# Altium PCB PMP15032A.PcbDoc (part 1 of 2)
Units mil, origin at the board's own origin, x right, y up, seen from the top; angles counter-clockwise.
Board outline 3900 x 2580 mil, 6 copper layers (Top Layer, Signal Layer 1, Signal Layer 2, Signal Layer 3, Signal Layer 4, Bottom Layer), stack 61.668 mil thick; 127 components, 51 nets, 282 pads, 427 vias.
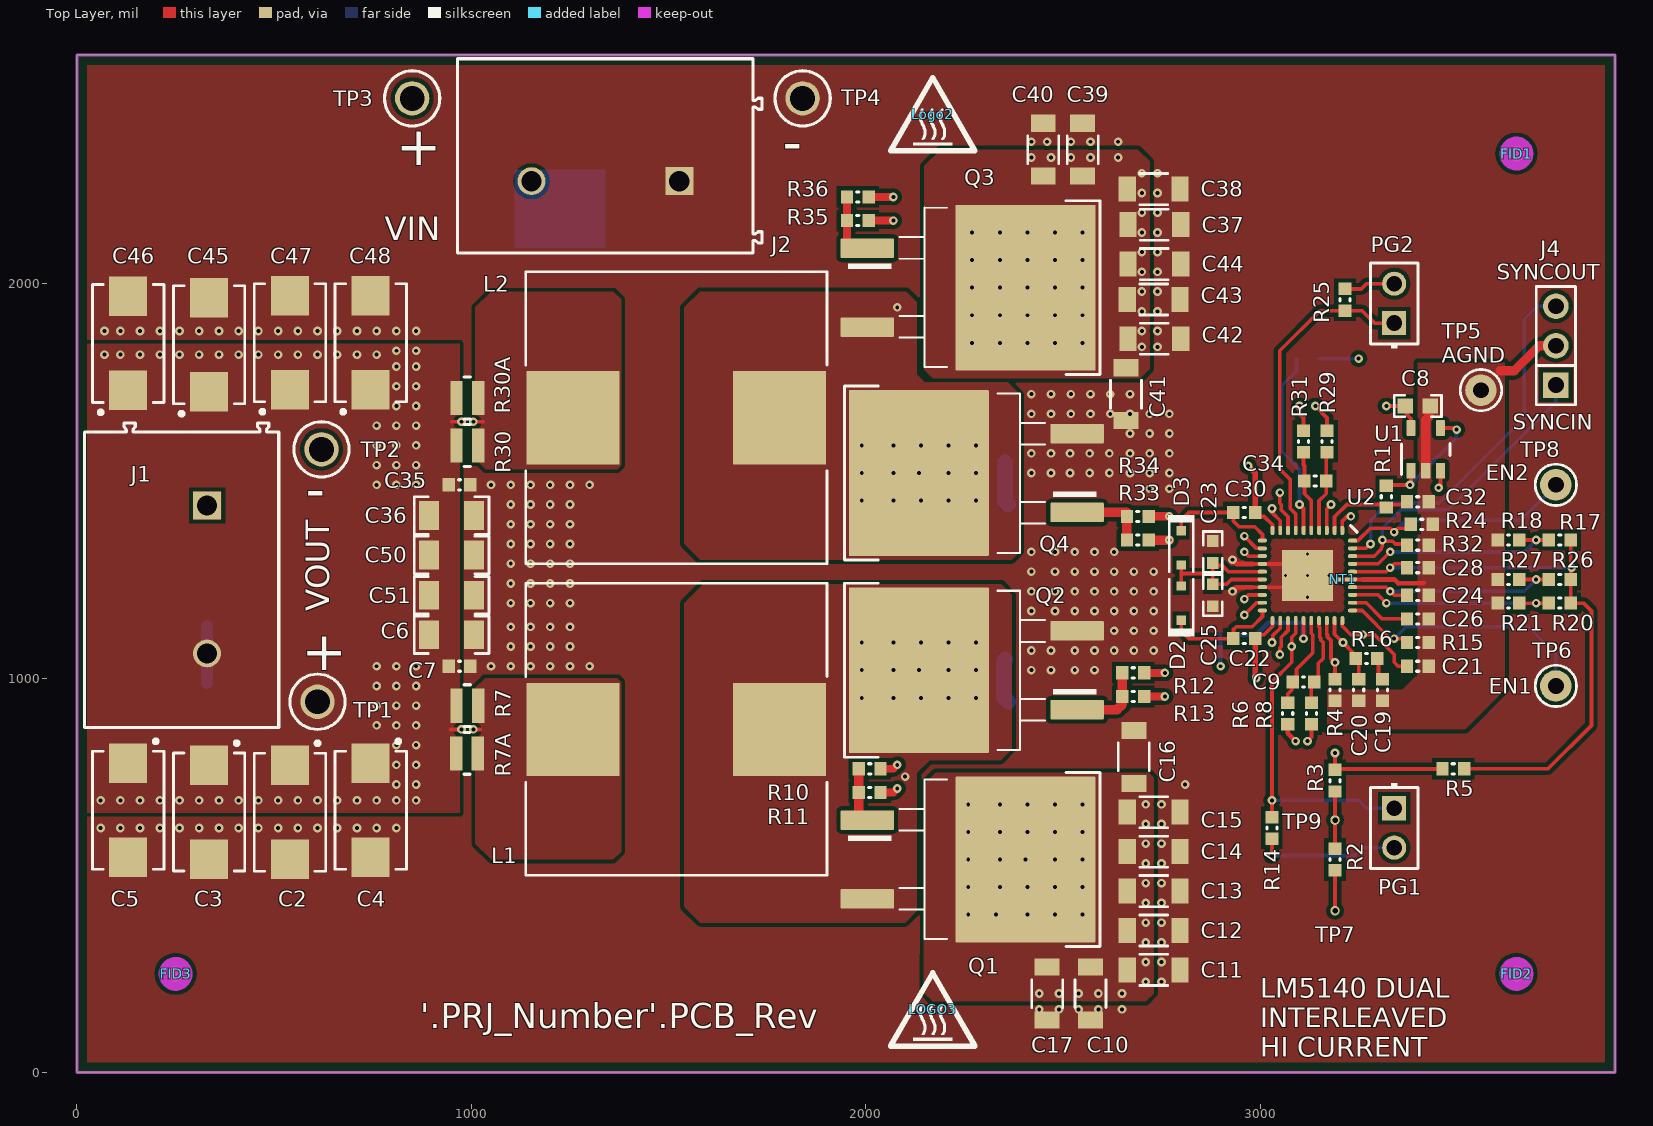
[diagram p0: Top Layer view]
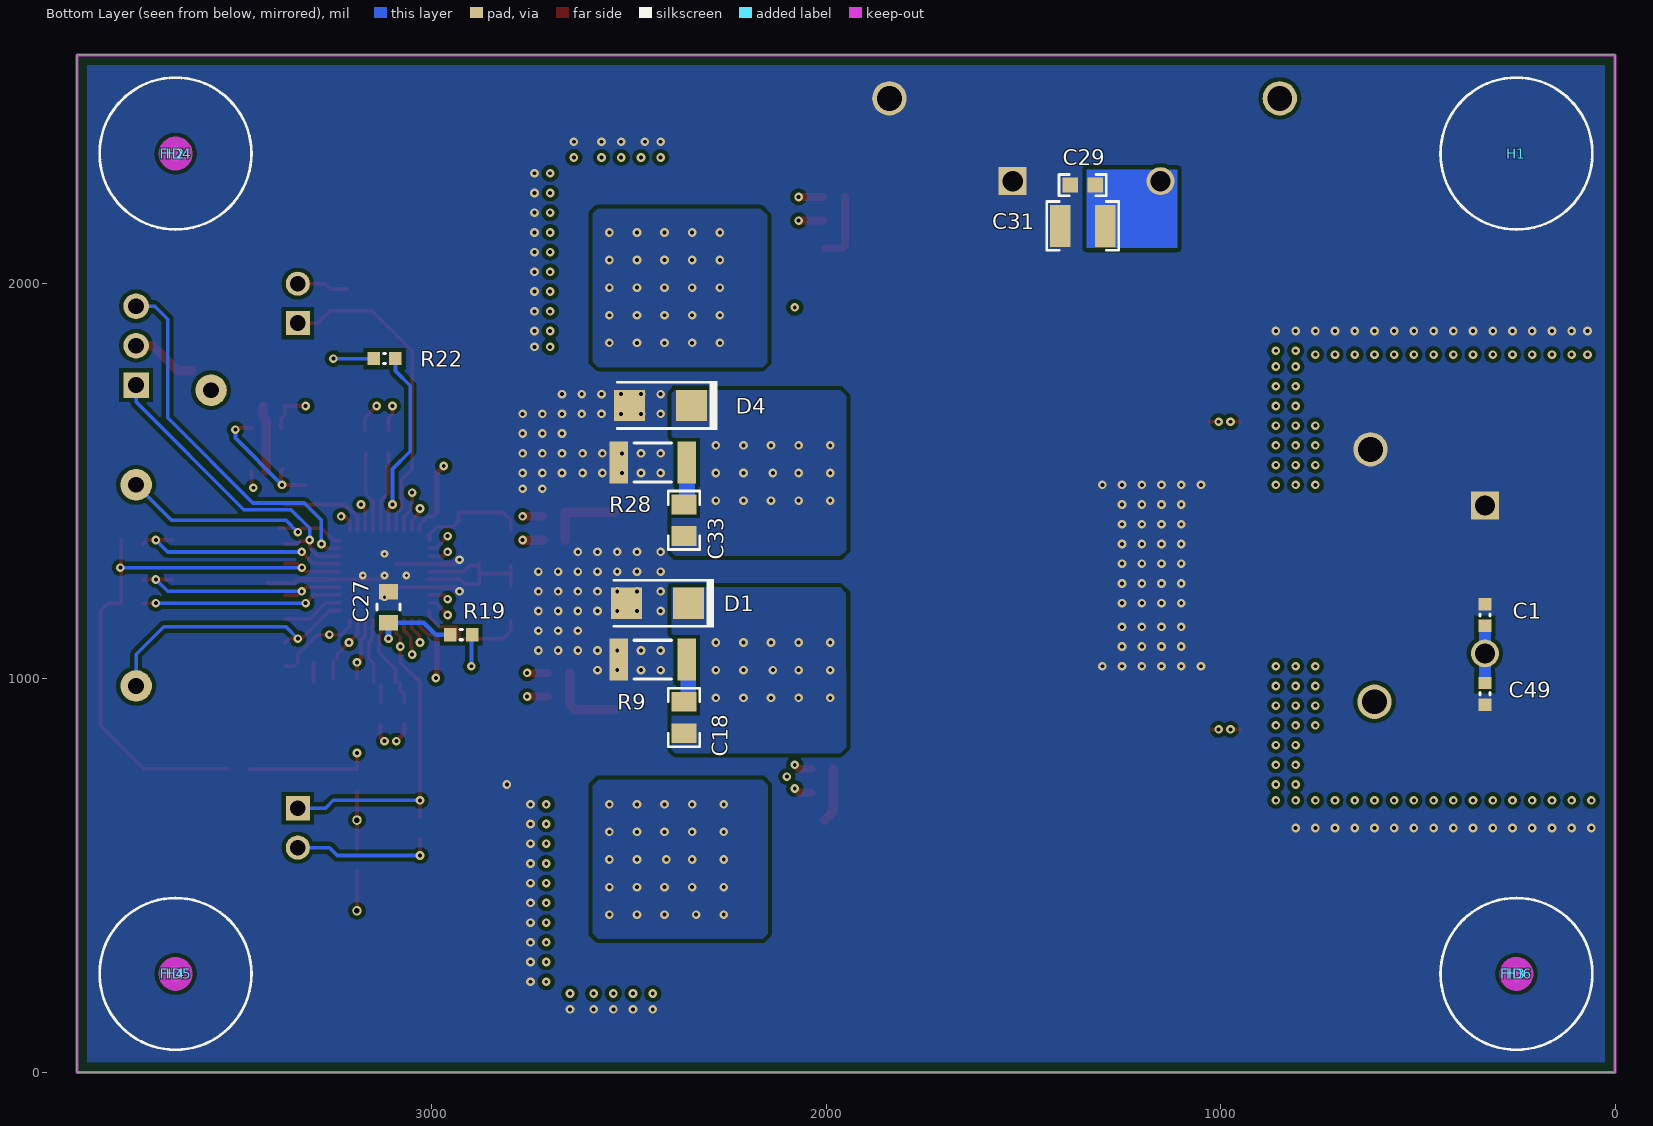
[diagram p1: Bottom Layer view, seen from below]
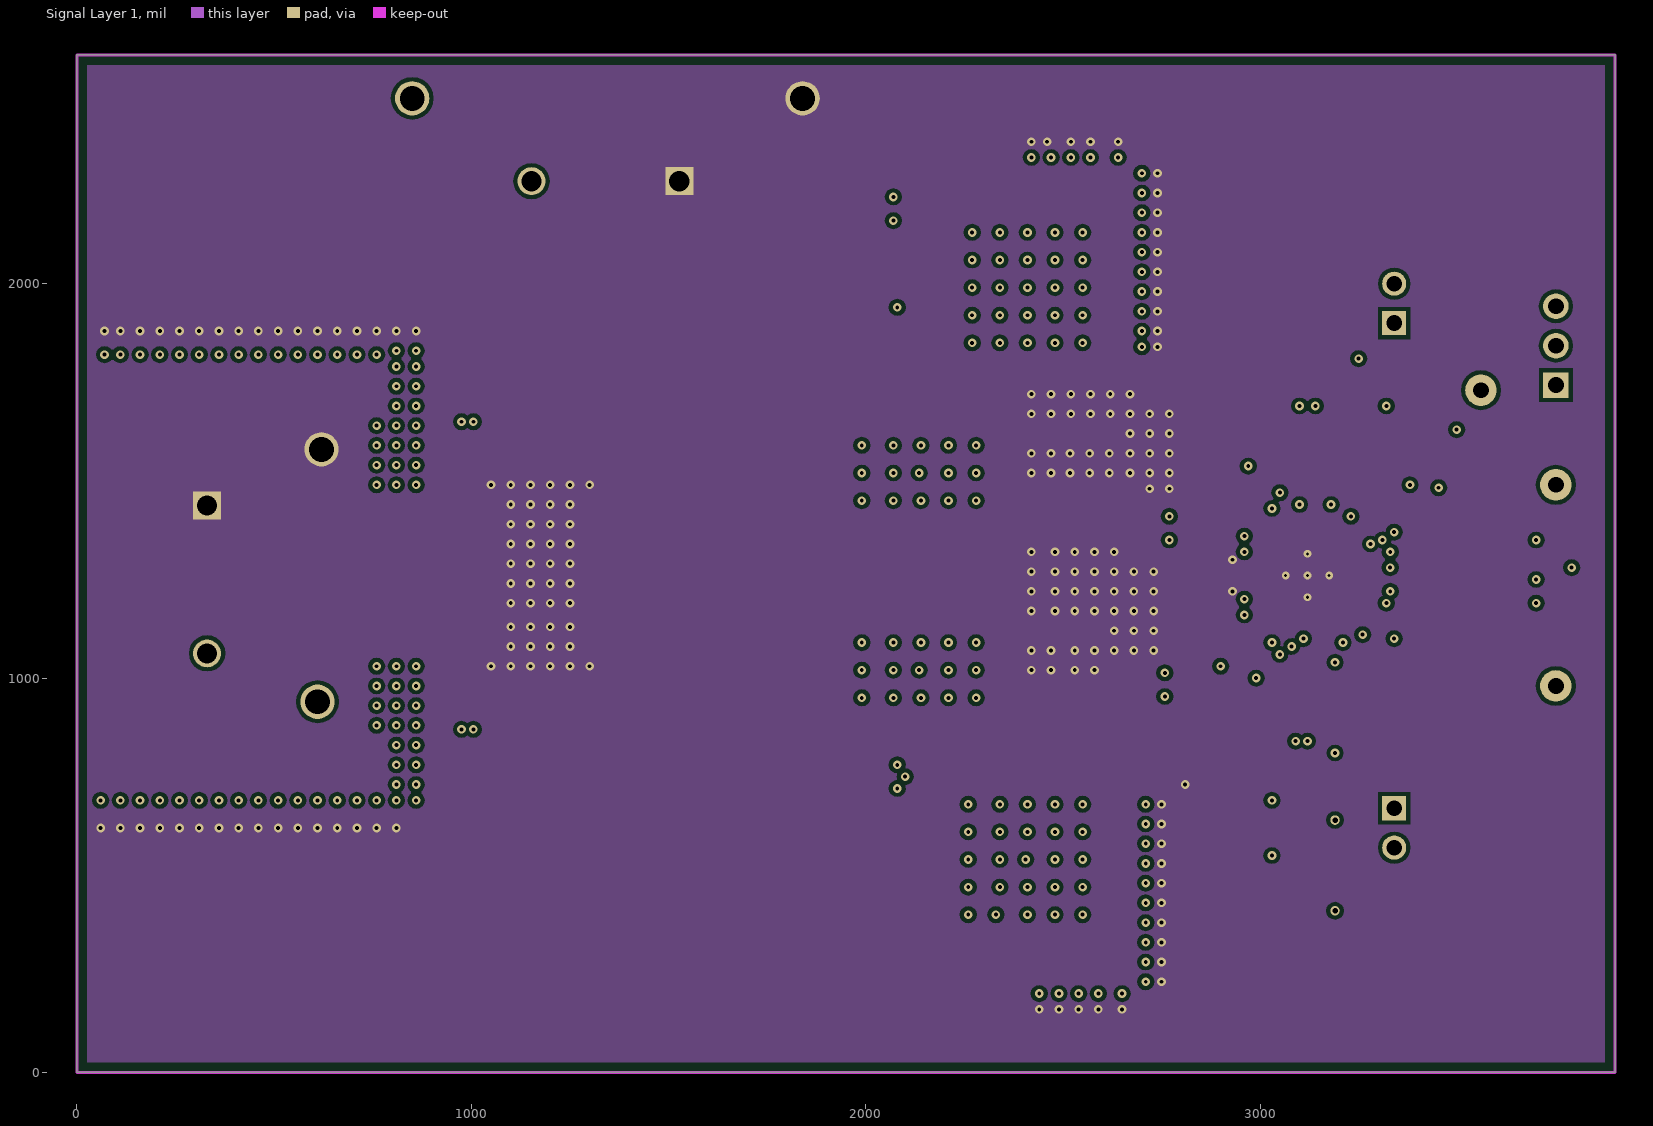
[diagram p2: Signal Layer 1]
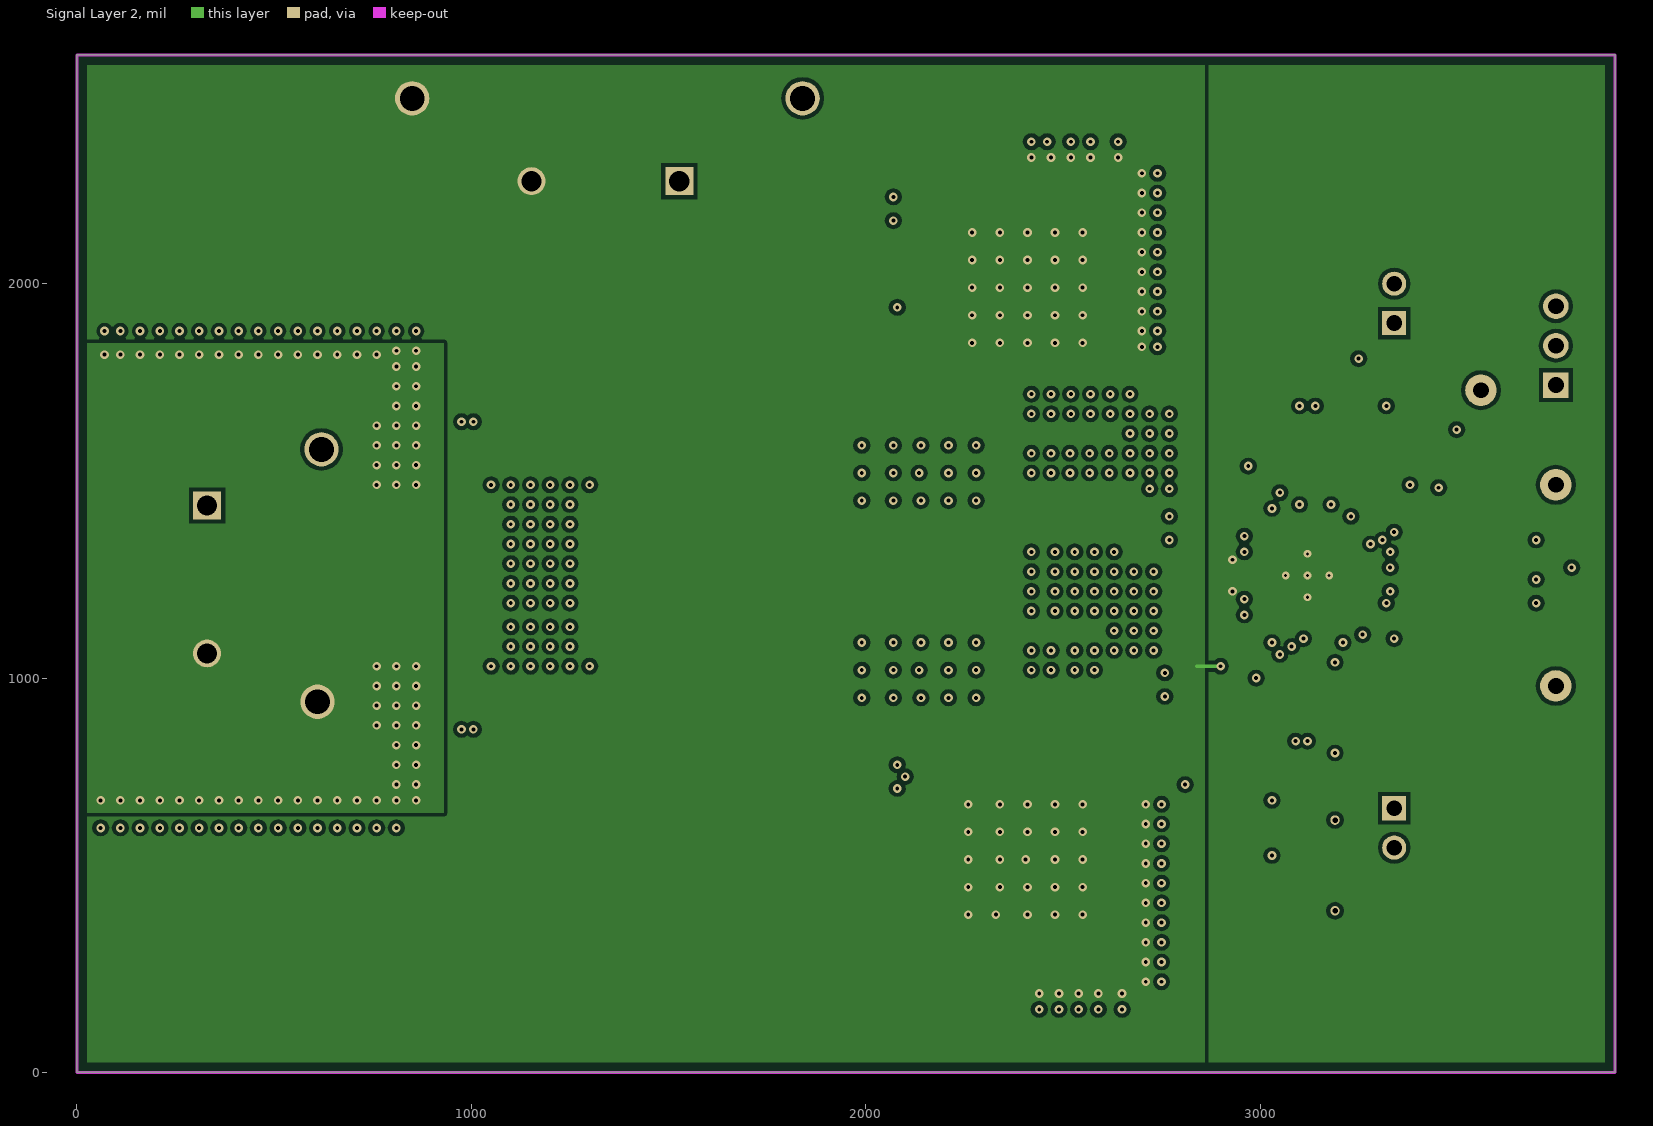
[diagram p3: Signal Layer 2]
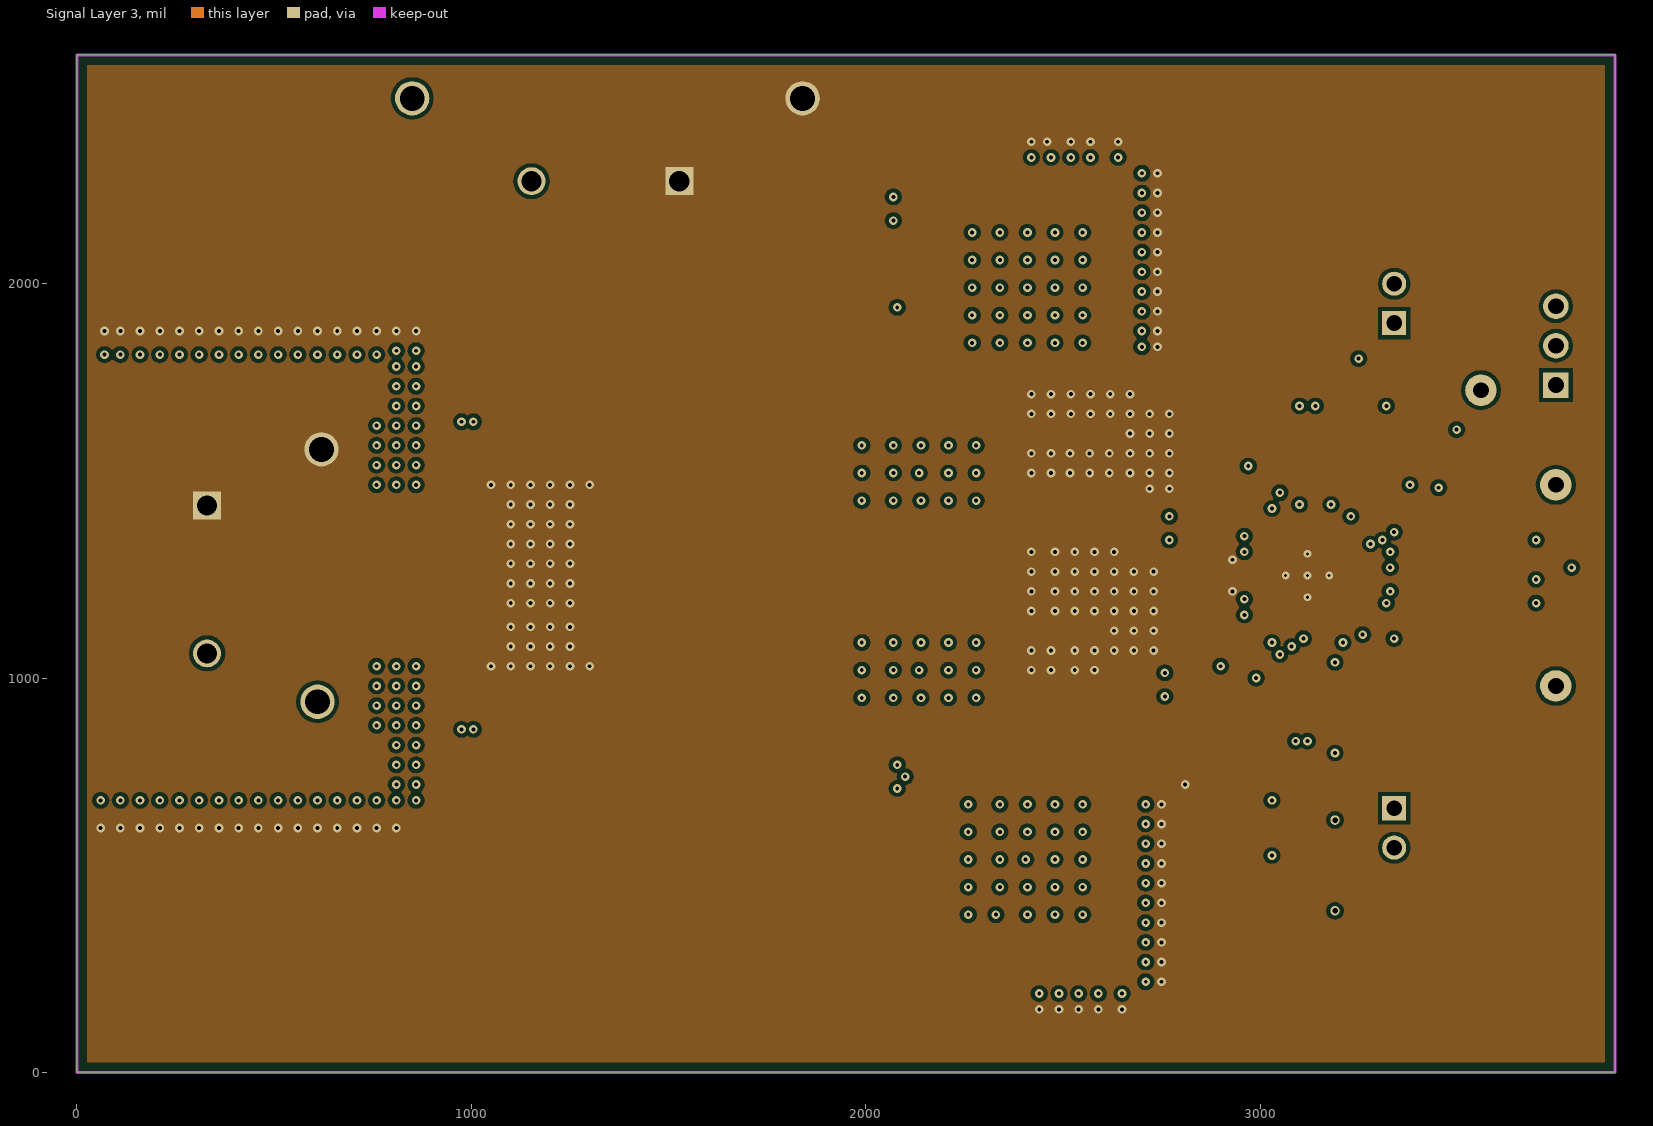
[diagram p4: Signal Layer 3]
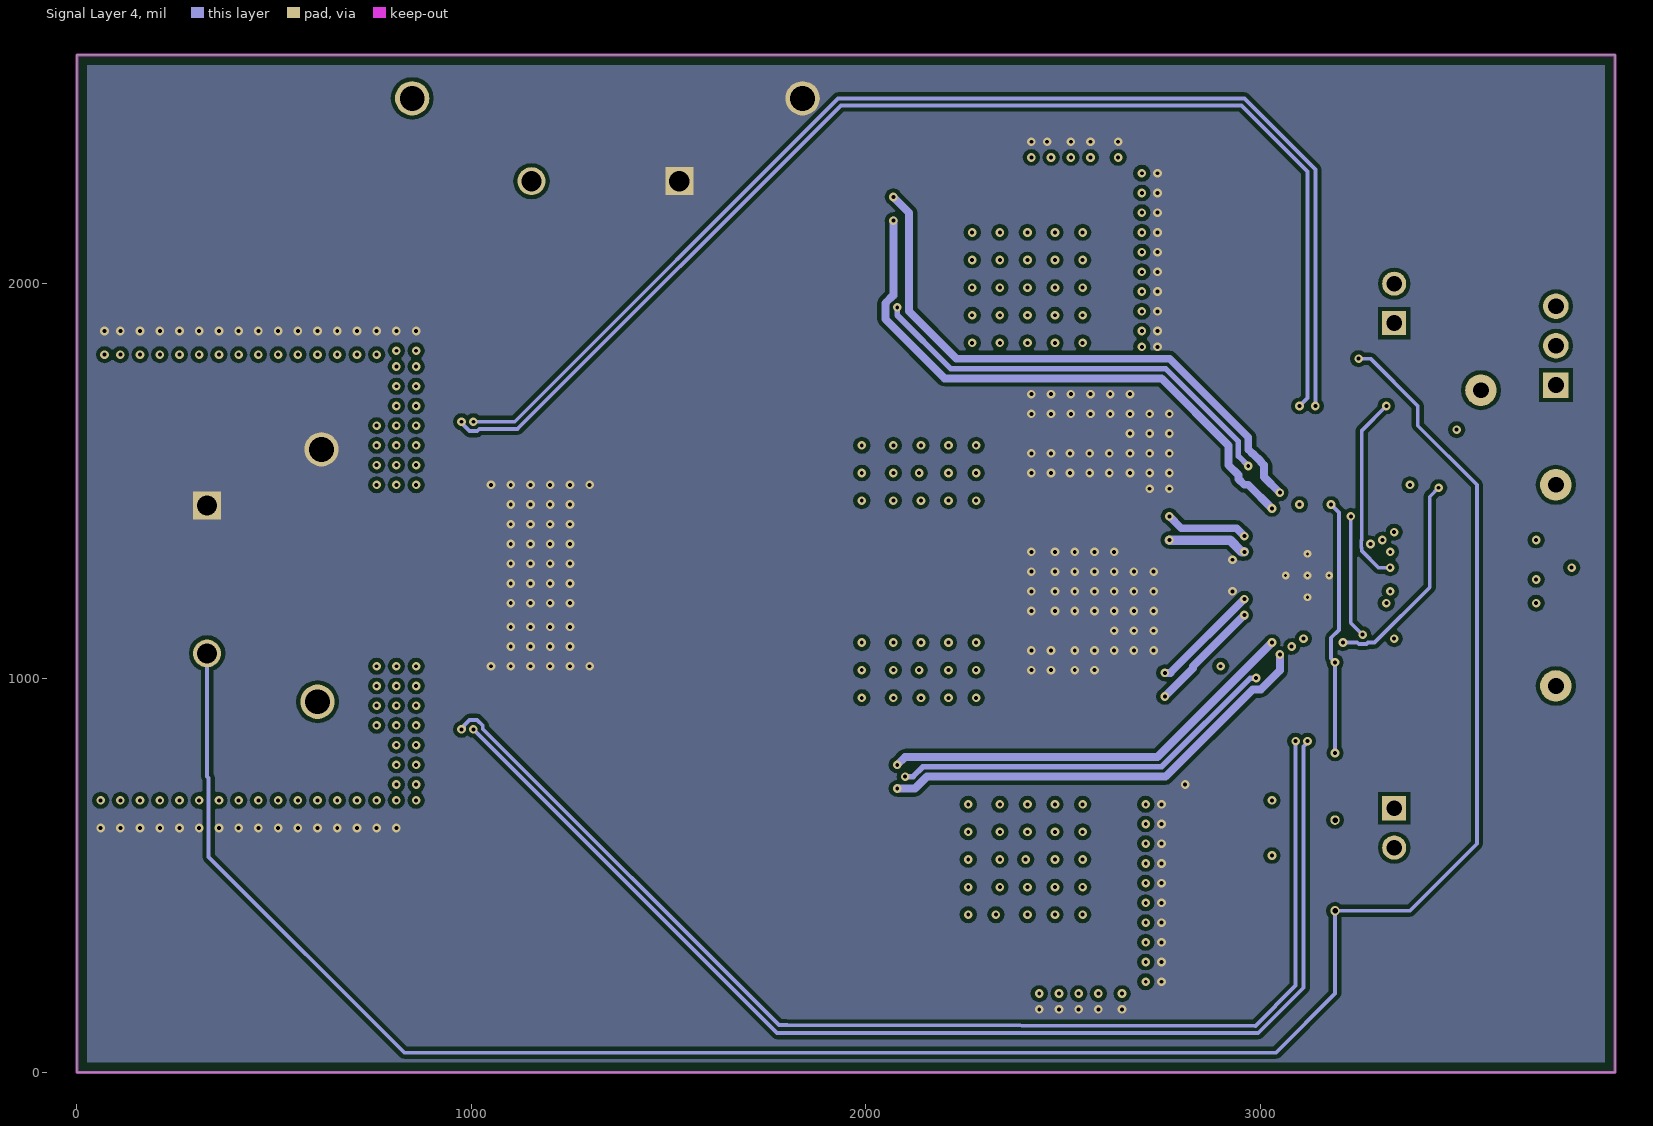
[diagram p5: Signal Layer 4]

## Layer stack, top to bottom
Top Solder: solder mask 0.4, Solder Resist, Dk 3.5
Top Layer: signal copper 2
Dielectric1: core 10, FR-4, Dk 4.8
Signal Layer 1: signal copper 1.417
Dielectric 2: prepreg 10, Dk 4.2
Signal Layer 2: signal copper 1.417
Dielectric 3: core 12, Dk 4.2
Signal Layer 3: signal copper 1.417
Dielectric 4: prepreg 10, Dk 4.2
Signal Layer 4: signal copper 1.417
Dielectric 5: core 10, Dk 4.2
Bottom Layer: signal copper 2
Bottom Solder: solder mask 0.4, Solder Resist, Dk 3.5

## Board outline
0,0 3900,0 3900,2580 0,2580

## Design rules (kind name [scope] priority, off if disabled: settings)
AcuteAngle [All] p1: minimum=4.50000000000000E+0001 checktracksonly=FALSE
AssemblyTestPointUsage [All] p1: valid=2
BoardOutlineClearance BoardOutlineClearance_MountingHoles [OnCopper and InComponentClass('Mounting Holes')] p1: gap=40
BoardOutlineClearance BoardOutlineClearance_Poly [OnCopper and IsPoly] p2: gap=25
BoardOutlineClearance [OnCopper and Not InComponentClass('Logo') and not InComponentClass('FiducialMark') and not InRegion(1000,500,4000,800) and not InPoly] p3: gap=40
Clearance Clearance_Keepouts [((IsTrack Or IsArc) And Not InPoly) And IsFree and IsKeepOut vs ((IsTrack Or IsArc) And Not InPoly) And IsFree and IsKeepOut] p1: gap=0
Clearance Clearance_Poly [InPolygon] p2: gap=10
Clearance [All] p3: gap=7.87
ComponentClearance ComponentClearance_Ficucial [HasFootprint('Fiducial10-20') vs HasFootprint('Bumpon_SJ61A2')] p1: gap=0 collisioncheckmode=3 verticalgap=0 showdistances=FALSE
ComponentClearance ComponentClearance_NetTie [HasFootprint('RWG0040A') vs HasFootprint('Net-Tie_10mil')] p2: gap=0 collisioncheckmode=3 verticalgap=0 showdistances=FALSE
ComponentClearance ComponentClearance_MountingHoles_FiducialMarks [InComponentClass('Mounting Holes') vs InComponentClass('FiducialMark')] p3: gap=50 collisioncheckmode=3 verticalgap=10 showdistances=FALSE
ComponentClearance ComponentClearance_Shunt [InComponentClass('Header') vs InComponentClass('Shunt')] p4: gap=0 collisioncheckmode=3 verticalgap=0 showdistances=FALSE
ComponentClearance ComponentClearance_Logo [InComponentClass('Logo')] p5: gap=50 collisioncheckmode=3 verticalgap=10 showdistances=FALSE
ComponentClearance ComponentClearance_ScrewToNut [(HasFootprint('NY PMS 440 0025 PH')) vs (HasFootprint('Keystone_1902C'))] p6: gap=5 collisioncheckmode=3 verticalgap=10 showdistances=FALSE
ComponentClearance ComponentClearance_MountingHoles [InComponentClass('Mounting Holes')] p7: gap=250 collisioncheckmode=3 verticalgap=100000 showdistances=FALSE
ComponentClearance ComponentClearance_SmallPassives [HasFootprint('0201*') or HasFootprint('0402*') or HasFootprint('0508') or HasFootprint('0603*') or HasFootprint('0612') or HasFootprint('0805*') or HasFootprint('0815*') or HasFootprint('0830*') or HasFootprint('1206*') or HasFootprint('1210*') or HasFootprint('1808*') or HasFootprint('1812*') or HasFootprint('1825*') or HasFootprint('2010*') or HasFootprint('2220*') or HasFootprint('2225*') or HasFootprint('2512*') or HasFootprint('2728*') or HasFootprint('3518*') vs HasFootprint('0201*') or HasFootprint('0402*') or HasFootprint('0508') or HasFootprint('0603*') or HasFootprint('0612') or HasFootprint('0805*') or HasFootprint('0815*') or HasFootprint('0830*') or HasFootprint('1206*') or HasFootprint('1210*') or HasFootprint('1808*') or HasFootprint('1812*') or HasFootprint('1825*') or HasFootprint('2010*') or HasFootprint('2220*') or HasFootprint('2225*') or HasFootprint('2512*') or HasFootprint('2728*') or HasFootprint('3518*')] p8: gap=14.96 collisioncheckmode=3 verticalgap=10 showdistances=FALSE
ComponentClearance ComponentClearance_THtoSMT [IsThruComponent vs IsSMTComponent] p9: gap=40 collisioncheckmode=3 verticalgap=30 showdistances=FALSE
ComponentClearance ComponentClearance_THtoTH [IsThruComponent vs IsThruComponent] p10: gap=30 collisioncheckmode=3 verticalgap=30 showdistances=FALSE
ComponentClearance [All] p11: gap=20 collisioncheckmode=3 verticalgap=10 showdistances=FALSE
DiffPairsRouting [All] p1: maxlimit=100 minlimit=10 mostfreqgap=10 toplayer_minwidth=15 toplayer_maxwidth=15 toplayer_prefwidth=15 midlayer1_minwidth=15 midlayer1_maxwidth=15 midlayer1_prefwidth=15 midlayer2_minwidth=15 midlayer2_maxwidth=15 midlayer2_prefwidth=15 midlayer3_minwidth=15 midlayer3_maxwidth=15 midlayer3_prefwidth=15 midlayer4_minwidth=15 midlayer4_maxwidth=15 midlayer4_prefwidth=15 bottomlayer_minwidth=15 bottomlayer_maxwidth=15 bottomlayer_prefwidth=15 maxuncoupledlength=1000
FabricationTestPointUsage TestPointUsage [All] p1: valid=2 allowmultiple=FALSE
FabricationTestpoint Testpoint [All] p1: side=3 testpointundercomponent=TRUE minsize=40 maxsize=100 preferedsize=60 minholesize=0 maxholesize=40 preferedholesize=32 testpointgrid=1 allowsidetop=TRUE allowsidebottom=TRUE usegrid=TRUE gridtolerance=0.01
FanoutControl Fanout_LCC [IsLCC] p1: bgadir=Out bgaviamode=Centered fanoutstyle=Auto fanoutdirection=Alternating viagrid=1 // Fanout_LCC (Default Rule)
FanoutControl Fanout_BGA [IsBGA] p2: bgadir=Out bgaviamode=Centered fanoutstyle=Auto fanoutdirection=Alternating viagrid=1 // Fanout_BGA (Default Rule)
FanoutControl Fanout_Default [All] p4: bgadir=Out bgaviamode=Centered fanoutstyle=Auto fanoutdirection=Alternating viagrid=1 // Fanout_Default (Default Rule)
FanoutControl Fanout_Small [(CompPinCount < 5)] p5: bgadir=Out bgaviamode=Centered fanoutstyle=Auto fanoutdirection=OutThenIn viagrid=1 // Fanout_Small (Default Rule)
HoleSize [All] p1: absolutevalues=TRUE maxlimit=251 minlimit=7.87 maxpercent=80.000 minpercent=20.000
MinimumAnnularRing MinimumAnnularRing_ThermalPadVias [IsVia and InAnyComponent] p1: minimumring=5.91
MinimumAnnularRing [All] p2: minimumring=5
MinimumSolderMaskSliver MinimumSolderMaskSliver_Logo [InComponentClass('Logo') vs InComponentClass('Logo')] p1: minsoldermaskwidth=0.7
MinimumSolderMaskSliver [All] p2: minsoldermaskwidth=3.94
PlaneConnect [All] p1: planeconnectstyle=Relief reliefexpansion=10 reliefentries=4 reliefconductorwidth=10 reliefairgap=10
PolygonConnect [All] p1: connectstyle=Direct reliefconductorwidth=10 reliefentries=4 polygonreliefangle="90 Angle" airgapwidth=10
RoutingVias ThermalPadVias [IsVia and InAnyComponent] p1: holewidth=7.87 width=19.68 viastyle="Through Hole" minholewidth=7.87 minwidth=19.68 maxholewidth=12.99 maxwidth=23.62
RoutingVias [All] p2: holewidth=10 width=22 viastyle="Through Hole" minholewidth=7.87 minwidth=20 maxholewidth=40 maxwidth=65
SilkToBoardRegionClearance [Not ((IsComment or IsDesignator) And (Hide <> 'False')) and not InRegion(1000,500,4000,800)] p1:
SilkToSilkClearance SilkToSilkClearance_Pb-FreeLogo [(HasFootprint('Pb-Free_Overlay_Medium') OR HasFootprint('Pb-Free_Overlay_Small')) vs (HasFootprint('Pb-Free_Overlay_Medium') OR HasFootprint('Pb-Free_Overlay_Small'))] p1: silktosilkclearance=0
SilkToSilkClearance [All] p2: silktosilkclearance=4
SilkToSolderMaskClearance SilkToComponentPadClearance [IsPad and InAnycomponent] p1: minsilkscreentomaskgap=5 clearancetoexposedcopper=TRUE
SilkToSolderMaskClearance "Silk to Solder Mask Opening" [All] p2: minsilkscreentomaskgap=4 clearancetoexposedcopper=FALSE
SolderMaskExpansion [All] p1: expansion=1.97
Width [All] p1: maxlimit=100 minlimit=6 preferedwidth=10 checkconnectedcopper=TRUE
15 further rules are at their usual default settings.

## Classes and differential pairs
component class PMP15032A: C1 C2 C3 C4 C5 C6 C7 C8 C9 C10 C11 C12 C13 C14 C15 C16 C17 C18 C19 C20 C21 C22 C23 C24 C25 C26 C27 C28 C29 C30 C31 C32 C33 C34 C35 C36 C37 C38 C39 C40 C41 C42 C43 C44 C45 C46 C47 C48 C49 C50 C51 D1 D2 D3 D4 J1 J2 J4 L1 L2 NT1 PG1 PG2 Q1 Q2 Q3 Q4 R1 R2 R3 R4 R5 R6 R7 R7A R8 R9 R10 R11 R12 R13 R14 R15 R16 R17 R18 R19 R20 R21 R22 R24 R25 R26 R27 R28 R29 R30 R30A R31 R32 R33 R34 R35 R36 TP1 TP2 TP3 TP4 TP5 TP6 TP7 TP8 TP9 U1 U2
component class PMP15032A-HW: FID1 FID2 FID3 FID4 FID5 FID6 H1 H2 H3 H4 Logo2 LOGO3

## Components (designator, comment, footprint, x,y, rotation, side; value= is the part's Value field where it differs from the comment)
C1 "GRM188R72A104KA35D" 0603L 330,1160 r270 bottom
C2 "100µF" 7343-31 540,660 r270 top
C3 "100µF" 7343-31 335.14,660.22 r270 top
C4 "100µF" 7343-31 744.86,664.86 r270 top
C5 "100µF" 7343-31 130,664.86 r270 top
C6 "C3216X5R1C476M160AB" 1206 950,1110 r0 top
C7 "GRM188R72A104KA35D" 0603L 970,1030 r180 top
C8 "0.1uF" 0603 3400,1690 r0 top
C9 "06031A330JAT2A" 0603L 3110,990 r180 top
C10 "CGA5L3X7S2A225M160AB" 1206_190 2570,200 r90 top
C11 "CGA5L3X7S2A225M160AB" 1206_190 2730,260 r180 top
C12 "CGA5L3X7S2A225M160AB" 1206_190 2730,360 r180 top
C13 "CGA5L3X7S2A225M160AB" 1206_190 2730,460 r180 top
C14 "CGA5L3X7S2A225M160AB" 1206_190 2730,560 r180 top
C15 "CGA5L3X7S2A225M160AB" 1206_190 2730,660 r180 top
C16 "CGA5L3X7S2A225M160AB" 1206_190 2680,800 r270 top
C17 "CGA5L3X7S2A225M160AB" 1206_190 2460,200 r90 top
C18 "08051A471JAT2A" 0805_HV 2360.58,900.06 r90 bottom
C19 "GRM188R71E103KA01D" 0603L 3310,970 r90 top
C20 "C0603C470J5GACTU" 0603L 3250,970 r270 top
C21 "C1608X7R1E105K080AB" 0603L 3400,1030 r0 top
C22 "CGA3E3X7R1H334K080AB" 0603L 2960,1100 r180 top
C23 "C0603C225M8PACTU" 0603_HV 2880,1320 r90 top
C24 "GRM188R71H103KA01D" 0603L 3400,1210 r0 top
C25 "C0603C225M8PACTU" 0603_HV 2880,1210 r90 top
C26 "GRM188R71H103KA01D" 0603L 3400,1150 r0 top
C27 "GRM21BR72A474KA73L" 0805_HV1 3110,1180 r270 bottom
C28 "C1608X7R1E105K080AB" 0603L 3400,1280 r0 top
C29 "GRM188R72A104KA35J" 0603 1350,2250 r0 bottom
C30 "CGA3E3X7R1H334K080AB" 0603L 2960,1420 r180 top
C31 "CGA6M3X7S2A475K200AB" 1210_220 1349.66,2146.77 r0 bottom
C32 "C0603C470J5GACTU" 0603L 3400,1447 r180 top
C33 "08051A471JAT2A" 0805_HV 2360.58,1400.06 r270 bottom
C34 "06031A330JAT2A" 0603L 3140,1500 r0 top
C35 "GRM188R72A104KA35D" 0603L 970,1490 r180 top
C36 "C3216X5R1C476M160AB" 1206 950,1412.02 r0 top
C37 "CGA5L3X7S2A225M160AB" 1206_190 2731.81,2149.78 r0 top
C38 "CGA5L3X7S2A225M160AB" 1206_190 2730,2240 r0 top
C39 "CGA5L3X7S2A225M160AB" 1206_190 2550,2340 r90 top
C40 "CGA5L3X7S2A225M160AB" 1206_190 2450,2340 r90 top
C41 "CGA5L3X7S2A225M160AB" 1206_190 2660,1720 r270 top
C42 "CGA5L3X7S2A225M160AB" 1206_190 2731.81,1860.22 r0 top
C43 "CGA5L3X7S2A225M160AB" 1206_190 2730,1960 r0 top
C44 "CGA5L3X7S2A225M160AB" 1206_190 2731.81,2049.78 r0 top
C45 "100µF" 7343-31 335.14,1845.14 r90 top
C46 "100µF" 7343-31 130,1848.59 r90 top
C47 "100µF" 7343-31 540,1850 r90 top
C48 "100µF" 7343-31 744.86,1850 r90 top
C49 "GRM188R72A104KA35D" 0603L 330,960 r90 bottom
C50 "C3216X5R1C476M160AB" 1206 950,1312.02 r0 top
C51 "C3216X5R1C476M160AB" 1206 950,1210 r0 top
D1 "B170-13-F" SMA 2428.19,1189.78 r0 bottom
D2 "PMEG6010CEJ,115" SOD-323F 2800,1190 r90 top
D3 "PMEG6010CEJ,115" SOD-323F 2800,1330 r270 top
D4 "B170-13-F" SMA 2420,1691.41 r0 bottom
FID1 "Fiducial" Fiducial10-20 3650,2330 r0 top
FID2 "Fiducial" Fiducial10-20 3650,250 r0 top
FID3 "Fiducial" Fiducial10-20 250,250 r0 top
FID4 "Fiducial" Fiducial10-20 3650,2330 r90 bottom
FID5 "Fiducial" Fiducial10-20 3650,250 r90 bottom
FID6 "Fiducial" Fiducial10-20 250,250 r90 bottom
H1 "SJ61A2" Bumpon_SJ61A2 250,2330 r180 bottom locked
H2 "SJ61A2" Bumpon_SJ61A2 3650,2330 r180 bottom locked
H3 "SJ61A2" Bumpon_SJ61A2 250,250 r180 bottom locked
H4 "SJ61A2" Bumpon_SJ61A2 3650,250 r180 bottom locked
J1 "1714971" Phoenix_1714971 330,1250 r270 top
J2 "1714971" Phoenix_1714971 1340,2260 r180 top
J4 "PBC03SAAN" PBC03SAAN 3750,1842.85 r90 top
L1 "7443556190" WE-HCB_1890 1520,870 r180 top
L2 "7443556190" WE-HCB_1890 1520,1660 r0 top
Logo2 "CAUTION HOT SURFACE" IEC_HotSurface_Small 2170,2430 r0 top (schematic designator LOGO2)
LOGO3 "CAUTION HOT SURFACE" IEC_HotSurface_Small 2170,160 r0 top
NT1 "Net-Tie" Net-Tie_10mil 3210,1250 r180 top net-tie
PG1 "PEC01DAAN" Sullins_PxC01DAAN 3340,620 r270 top
PG2 "PEC01DAAN" Sullins_PxC01DAAN 3340,1950 r90 top
Q1 "FDD9407L_F085" DDPAK 2250,540 r0 top
Q2 "FDD9407L_F085" DDPAK 2290,1020 r180 top
Q3 "FDD9407L_F085" DDPAK 2250,1990 r0 top
Q4 "FDD9407L_F085" DDPAK 2290,1520 r180 top
R1 "0" 0603L 3320,1460 r90 top
R2 "CRCW060310R0FKEA" 0603L 3190,540 r270 top
R3 "CRCW060363K4FKEA" 0603L 3190,740 r270 top
R4 "CRCW060320K0FKEA" 0603L 3190,970 r90 top
R5 "0" 0603L 3490,770 r0 top
R6 "CRCW06030000Z0EA" 0603L 3070,910 r270 top
R7 "KRL2012M-R005-F-T1" KRL2012 990,930 r0 top
R7A "KRL2012M-R005-F-T1" KRL2012 989.18,809.19 r0 top
R8 "CRCW060349R9FKEA" 0603L 3130,910 r270 top
R9 "CRCW20108R20JNEF" 2010L 2440,1046.77 r180 bottom
R10 "CRCW06034R99FKEA" 0603L 2010,770 r0 top
R11 "CRCW06030000Z0EA" 0603L 2010,710 r0 top
R12 "CRCW06034R99FKEA" 0603L 2678.31,1013.27 r0 top
R13 "CRCW06034R99FKEA" 0603L 2678.31,953.27 r0 top
R14 "CRCW060310K0JNEA" 0603L 3030,620 r90 top
R15 "100k" 0603L 3400,1090 r180 top
R16 "CRCW060310K0FKEA" 0603L 3270,1050 r180 top
R17 "RC0603JR-070RL" 0603L 3760,1350 r0 top
R18 "0" 0603L 3630,1350 r180 top
R19 "CRCW06030000Z0EA" 0603L 2925.55,1110 r180 bottom
R20 "CRCW06030000Z0EA" 0603L 3760,1190 r180 top
R21 "0" 0603L 3630,1190 r0 top
R22 "0" 0603L 3120,1810 r180 bottom
R24 "100k" 0603L 3410,1390 r180 top
R25 "CRCW060310K0JNEA" 0603L 3215.29,1959.14 r90 top
R26 "0" 0603L 3760,1250 r0 top
R27 "0" 0603L 3630,1250 r180 top
R28 "CRCW20108R20JNEF" 2010L 2440,1546.77 r180 bottom
R29 "CRCW060349R9FKEA" 0603L 3170,1600 r90 top
R30 "KRL2012M-R005-F-T1" KRL2012 990,1590 r180 top
R30A "KRL2012M-R005-F-T1" KRL2012 990,1710 r180 top
R31 "CRCW06030000Z0EA" 0603L 3110,1600 r90 top
R32 "CRCW060310K0FKEA" 0603L 3400,1337 r180 top
R33 "CRCW06034R99FKEA" 0603L 2690,1350 r180 top
R34 "CRCW06034R99FKEA" 0603L 2690,1410 r180 top
R35 "CRCW06034R99FKEA" 0603L 1980,2160 r180 top
R36 "CRCW06030000Z0EA" 0603L 1980,2220 r180 top
TP1 "+VOUT1" Keystone5010 610,940 r0 top
TP2 "GND" Keystone5011 620,1580 r0 top
TP3 "+VIN" Keystone5010 850,2470 r0 top
TP4 "GND" Keystone5011 1840,2470 r0 top
TP5 "5001" Keystone5001 3560,1730 r0 top
TP6 "EN1" Keystone5002 3750,980 r90 top
TP7 "TESTPOINT" TP_VIA_024RND014 3190,410 r90 top
TP8 "EN2" Keystone5002 3750,1490 r180 top
TP9 "TESTPOINT" TP_VIA_024RND014 3190,640 r90 top
U1 "LMP7701MF" DBV0005A_N 3420,1580 r90 top
U2 "LM5140QRWGRQ1" RWG0040A 3120,1260 r270 top

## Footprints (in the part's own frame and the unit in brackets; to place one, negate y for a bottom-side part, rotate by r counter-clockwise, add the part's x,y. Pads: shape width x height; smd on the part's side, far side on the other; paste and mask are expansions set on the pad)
0603 [mm] "0603 from SM-752 data"
  rect 1x0.95 smd: 1(-0.8,0) 2(0.8,0)
  silkscreen extent -1.52,-0.69 1.52,0.69, body extent -0.87,-0.47 0.87,0.47, height 1
0603_HV [mil] "Ernesto recommended land pattern.  26 mil between pads."
  rect 30x30 smd: 1(-28,0) 2(28,0)
  silkscreen extent -52,-24 52,24, body extent -34,-19 34,19, height 39
0603L [mm] "0603 from SM-752 data"
  rect 0.8x0.85 smd: 1(-0.7,0) 2(0.7,0)
  silkscreen extent -0.07,-0.33 0.07,0.33, body extent -0.87,-0.47 0.87,0.47, height 1
0805_HV [mil] "0805 with 30mil clearance between pads"
  rect 50x63 smd: 1(-40,0) 2(40,0)
  silkscreen extent -74,-40 74,40, body extent -43,-29 43,29, height 57
0805_HV1 [mm] "Custom footprint based on analyzing multiple manufacturer recommendations"
  rrect10% 1x1.25 smd: 1(-1,0) 2(1,0)
  silkscreen extent -0.2,-0.75 0.2,0.75, body extent -1.1,-0.72 1.1,0.73, height 1.45
1206 [mm] "1206 from SM-752 data"
  rect 1.3x1.85 smd: 1(-1.45,0) 2(1.45,0)
  silkscreen extent -2.4,-1.21 2.4,1.21, body extent -1.7,-0.9 1.7,0.9, height 1.35
1206_190 [mm] "1206_190"
  rect 1.1x1.6 smd: 1(-1.7,0) 2(1.7,0)
  silkscreen extent -0.9,-1 0.9,1, body extent -1.75,-0.95 1.75,0.95, height 1.9
1210_220 [mm] "1210"
  rect 1.3x2.7 smd: 1(-1.45,0) 2(1.45,0)
  silkscreen extent -2.32,-1.57 2.32,1.57, body extent -1.7,-1.35 1.7,1.35, height 2.2
2010L [mm]
  rect 1.2x2.7 smd: 1(-2.2,0) 2(2.2,0)
  silkscreen extent -1.2,-1.25 1.2,1.25, body extent -2.73,-1.45 2.73,1.45, height 1.66
7343-31 [mm] "Medium Density based on Kemet T495 dimensions"
  rect 2.55x2.45 smd: 1(-3.025,0) 2(3.025,0)
  silkscreen extent -4.56,-2.3 3.8,2.3, body extent -3.8,-2.3 3.8,2.3, height 3.1
Bumpon_SJ61A2 [mil] "3M Hemispherical Bumpon transparent"
  round 1 on Mech4: 0(0,0)
  silkscreen extent -192,-192 192,192, body extent -193,-192 193,192, height 250
DBV0005A_N [mm] "SOT23, 5-Leads, Body 2.9x1.6mm, Pitch 0.95mm, Lead Span 2.8mm, IPC Medium Density"
  rrect17% 1x0.6 smd: 1(-1.375,0.95) 2(-1.375,0) 3(-1.375,-0.95) 4(1.375,-0.95) 5(1.375,0.95)
  silkscreen extent -1.63,-1.55 0.38,1.55, body extent -1.42,-1.46 1.42,1.46, height 1.09
DDPAK [mil] "D2-PAK, 3-Pads, Body 9.7x10.4mm (max), TO-263AB, using Vishay Silionix recommended pad sizes"
  rrect8% 135x49.49 smd: 1(-246.06,100) 3(-246.06,-100)
  rrect1% 355x420 smd paste-181.1: 4(155.51,0)
  silkscreen extent -295,-220 344,220, body extent -295,-202 324,202, height 180
Fiducial10-20 [mm]
  round 1 smd mask+0.5: 1(0,0)
  Top Layer keep-out circle w1.178: c0,0 r0.5
IEC_HotSurface_Small [mil]
  silkscreen extent -107,-93 107,92
Keystone5001 [mil] "For Keystone 500x miniature loop terminals"
  round 80 hole 40: 1(0,0)
  silkscreen extent -52,-52 52,52, body extent -49,-49 49,49, height 182
Keystone5002 [mil] "For Keystone 500x miniature loop terminals"
  round 80 hole 40: 1(0,0)
  silkscreen extent -52,-52 52,52, body extent -49,-49 49,49, height 182
Keystone5010 [mil] "Keystone Multipurpose loops"
  round 87 hole 63: 1(0,0)
  silkscreen extent -70,-70 70,70, body extent -63,-63 63,62, height 319
Keystone5011 [mil] "Keystone Multipurpose loops"
  round 87 hole 63: 1(0,0)
  silkscreen extent -70,-70 70,70, body extent -63,-63 63,62, height 319
KRL2012 [mm] "SUSUMU"
  rect 0.8x2.2 smd: 1(-0.7,0) 2(0.7,0)
  silkscreen extent -0.2,-1.35 0.2,1.35, body extent -0.72,-1.1 0.72,1.1, height 0.7
Net-Tie_10mil [mil] "10mil net tie, no solder mask opening, no solder paste"
  rect 10x10 smd paste-5 mask-5: 1(-10,0) 2(10,0)
  Top Layer region: -6,5 6,5 6,-5 -6,-5
PBC03SAAN [mm] "Sullins 100mil, 1x3, 230 mil above insulator"
  rect 1.65x1.65 hole 1.016: 1(-2.54,0)
  round 1.65 hole 1.016: 2(0,0) 3(2.54,0)
  silkscreen extent -3.81,-1.27 3.81,1.27, body extent -3.81,-1.27 3.81,1.27, height 8.38
Phoenix_1714971 [mm] "Receptacle, 9.52mm, 2x1, TH"
  rect 1.8x1.8 hole 1.3: 1(-4.76,0)
  round 1.8 hole 1.3: 2(4.76,0)
  silkscreen extent -10.08,-7.89 9.53,4.61, body extent -10.09,-7.9 9.52,4.6, height 22
RWG0040A [mm] "QFN, 40-Leads, Body 6x6mm, Pitch 0.5mm, Thermal Pad 3.3 x 3.3mm, TI Recommended"
  rrect7% 1.43x1.43 on Top Paste: 0(-0.815,0.815) 0(-0.815,-0.815) 0(0.815,0.815) 0(0.815,-0.815)
  rrect100% 0.6x0.25 smd: 1(-2.9,2.25) 2(-2.9,1.75) 3(-2.9,1.25) 4(-2.9,0.75) 5(-2.9,0.25) 6(-2.9,-0.25) 7(-2.9,-0.75) 8(-2.9,-1.25) 9(-2.9,-1.75) 10(-2.9,-2.25) 21(2.9,-2.25) 22(2.9,-1.75) 23(2.9,-1.25) 24(2.9,-0.75) 25(2.9,-0.25) 26(2.9,0.25) 27(2.9,0.75) 28(2.9,1.25) 29(2.9,1.75) 30(2.9,2.25)
  rrect100% 0.25x0.6 smd: 11(-2.25,-2.9) 12(-1.75,-2.9) 13(-1.25,-2.9) 14(-0.75,-2.9) 15(-0.25,-2.9) 16(0.25,-2.9) 17(0.75,-2.9) 18(1.25,-2.9) 19(1.75,-2.9) 20(2.25,-2.9) 31(2.25,2.9) 32(1.75,2.9) 33(1.25,2.9) 34(0.75,2.9) 35(0.25,2.9) 36(-0.25,2.9) 37(-0.75,2.9) 38(-1.25,2.9) 39(-1.75,2.9) 40(-2.25,2.9)
  rrect3% 3.3x3.3 smd paste-1.65: 41(0,0)
  silkscreen extent -3.21,2.78 -2.79,3.2, body extent -3,-3 3,3, height 0.86
SMA [mm] "Molded Diode, 2-Leads, Body 4.3x2.6mm, IPC Medium Density, based on OnSemi component dimensions and land pattern"
  rect 2x2 smd: 1(-2,0) 2(2,0)
  silkscreen extent -3.66,-1.57 2.79,1.57, body extent -2.6,-1.3 2.6,1.3, height 2.42
SOD-323F [mm] "NXP recommended land pattern"
  rect 0.6x0.6 smd paste-0.05: 1(-1.1,0) 2(1.1,0)
  silkscreen extent -2.13,-0.86 1.53,0.86, body extent -1.35,-0.67 1.35,0.68, height 0.79
Sullins_PxC01DAAN [mm] "Header, 2.54mm, 1x2, TH"
  rect 1.55x1.55 hole 1.016: 1(-1.27,0)
  round 1.55 hole 1.016: 2(1.27,0)
  silkscreen extent -2.9,-1.53 2.61,1.53, body extent -2.61,-1.53 2.61,1.53, height 8.71
TP_VIA_024RND014 [mil] "TP_VIA_024RND014"
  round 24 hole 14: 1(0,0)
WE-HCB_1890 [mm] "WURTH ELEKTRONIK"
  rect 6x6 smd: 1(-6.65,0) 2(6.65,0)
  silkscreen extent -9.7,-9.4 9.7,9.4, body extent -9.65,-9.35 9.65,9.35, height 9.2

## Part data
C1 C7 C35 C49: "CAP, CERM, 0.1uF, 100V, +/-10%, X7R, 0603"
C2 C3 C4 C5 C45 C46 C47 C48: library part T598D107M010ATE025, "CAP TANT POLY 100UF 10V 2917"
C6 C36 C50 C51: "CAP, CERM, 47uF, 16V, +/-15%, X5R, 1206"
C8: library part C0603C104K4RACTU, "CAP, CERM, 0.1uF, 16V, +/-10%, X7R, 0603"
C9 C34: "CAP, CERM, 33 pF, 100 V, +/- 5%, C0G/NP0, 0603"
C10 C11 C12 C13 C14 C15 C16 C17 C37 C38 C39 C40 C41 C42 C43 C44: "CAP, CERM, 2.2 µF, 100 V, +/- 20%, X7S, AEC-Q200 Grade 1, 1206_190"
C18 C33: "CAP, CERM, 470 pF, 100 V, +/- 5%, C0G/NP0, 0805"
C19: "CAP, CERM, 0.01 µF, 25 V, +/- 10%, X7R, 0603"
C20 C32: "CAP, CERM, 47 pF, 50 V, +/- 5%, C0G/NP0, 0603"
C21 C28: "CAP, CERM, 1 µF, 25 V, +/- 10%, X7R, 0603"
C22 C30: "CAP, CERM, 0.33 µF, 50 V, +/- 10%, X7R, AEC-Q200 Grade 1, 0603"
C23 C25: "CAP, CERM, 2.2 µF, 10 V, +/- 20%, X5R, 0603"
C24 C26: "CAP, CERM, 0.01uF, 50V, +/-10%, X7R, 0603"
C27: "CAP, CERM, 0.47uF, 100V, +/-10%, X7R, 0805"
C29: "CAP, CERM, 0.1 µF, 100 V, +/- 10%, X7R, 0603"
C31: "CAP, CERM, 4.7 µF, 100 V, +/- 10%, X7S, AEC-Q200 Grade 1, 1210"
D1 D4: "Diode, Schottky, 70V, 1A, SMA"
D2 D3: "Diode, Schottky, 60 V, 1 A, SOD-323F"
FID1 FID2 FID3 FID4 FID5 FID6: "Fiducial mark.  There is nothing to buy or mount."
H1 H2 H3 H4: "Bumpon, Hemisphere, 0.375 X 0.235, Black"
J1 J2: "Receptacle, 9.52mm, 2x1, TH"
J4: "Header, 100mil, 3x1, Gold, TH"
L1 L2: "Inductor, Shielded Drum Core, WE-Superflux200, 1.9 µH, 32.5 A, 0.0012 ohm, SMD"
Logo2 LOGO3: library part IEC_HotSurface, "IEC 61010-1 Hot Surface Warning"
NT1: "Single point connection between nets."
PG1 PG2: "Header, 2.54mm, 1x2, Tin, Black, TH"
Q1 Q2 Q3 Q4: "MOSFET N-CH 40V 100A"
R1: library part CRCW06030000Z0EA, "RES, 0 ohm, 5%, 0.1W, 0603"
R2: "RES, 10.0, 1%, 0.1 W, 0603"
R3: "RES, 63.4 k, 1%, 0.1 W, 0603"
R4: "RES, 20.0 k, 1%, 0.1 W, 0603"
R5 R18 R21 R22 R26 R27: library part CRCW06030000Z0EA, "RES, 0, 5%, 0.1 W, 0603"
R6 R11 R19 R20 R31 R36: "RES, 0, 5%, 0.1 W, 0603"
R7 R7A R30 R30A: "RES, 0.005, 1%, 1 W, AEC-Q200 Grade 0, 0508"
R8 R29: "RES, 49.9, 1%, 0.1 W, 0603"
R9 R28: "RES, 8.2, 5%, 0.75 W, 2010"
R10 R12 R13 R33 R34 R35: "RES, 4.99, 1%, 0.1 W, 0603"
R14 R25: "RES, 10 k, 5%, 0.1 W, 0603"
R15 R24: library part CRCW0603100KJNEA, "RES, 100 k, 5%, 0.1 W, 0603"
R16 R32: "RES, 10.0 k, 1%, 0.1 W, 0603"
R17: "RES, 0 ohm, 5%, 0.1W, 0603"
TP1 TP3: library part 5010, "Test Point, Multipurpose, Red, TH"
TP2 TP4: library part 5011, "Test Point, Multipurpose, Black, TH"
TP5: "Test Point, Miniature, Black, TH"
TP6 TP8: library part 5002, "Test Point, Miniature, White, TH"
TP7 TP9: "TEST POINT.  No entry in BOM."
U1: "Precision, Single CMOS Input R-R I/O, 12V Op Amp, DBV0005A"
U2: library part LM5140RHA, "Wide Input Range Dual Synchronous Buck Controller, RHA0040C"

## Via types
v1: diameter 22, hole 10, Top Layer to Bottom Layer, tented both sides, 319 vias
v2: diameter 22, hole 10, Top Layer to Bottom Layer, 102 vias
v3: diameter 19.68, hole 7.87, Top Layer to Bottom Layer, 5 vias
v4: diameter 22, hole 10, Top Layer to Bottom Layer, tented bottom, 1 vias

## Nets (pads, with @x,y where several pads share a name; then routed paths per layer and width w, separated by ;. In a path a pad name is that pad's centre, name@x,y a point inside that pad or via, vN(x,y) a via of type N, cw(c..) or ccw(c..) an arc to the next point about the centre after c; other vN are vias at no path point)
AGND: C8.2 C19.1 C20.2 C21.2 C24.2 C26.2 C28.2 C32.1 J4.2 NT1.1 R4.1 R15.1 R18.2 R21.1 R24.1 R27.2 R32.1 TP5.1 U1.2 U2.35 | length 534.1
  Top Layer w9.5: NT1.1@3220,1250 U2.35@3234.02,1250 ; U2.35@3234.17,1250.16 3259.84,1250.16
  Top Layer w12: 3259.84,1250.16 3340,1250 3350,1240 3350.34,1240 3350.95,1240.61 3414.16,1240.61 3414.96,1241.41
  Top Layer w24: U1.2@3420,1525.87 3420,1655.16 3427.56,1662.72 C8.2@3427.56,1690 ; 3609.04,1779.24 3644.23,1779.24 3707.84,1842.85 J4.2@3750,1842.85
COMP1: C20.1 R16.2 U1.3 U2.29 | length 754.2
  Top Layer w9.5: U2.29@3188.9,1145.83 3188.9,1111.1 v1(3210,1090) 3240,1060 R16.2@3240,1048.7 ; C20.1@3250,997.56 R16.2@3250,1042.44 ; v1(3452.6,1482.6) 3457.4,1482.6 U1.3@3457.4,1525.87
  Signal Layer 4 w9.5: v1(3210,1090) 3246.59,1090 3250.21,1086.38 3269.79,1086.38 3273.41,1090 3290,1090 3430,1230 3430,1460 v1(3452.6,1482.6)
COMP2: C32.2 R1.1 U2.2 | length 231.2
  Top Layer w9.5: U2.2@3188.9,1374.17 3188.9,1408.9 3220,1440 C32.2@3372.44,1440
CS1: C9.1 R8.1 U2.27 | length 210.2
  Top Layer w9.5: R8.1@3130,937.56 C9.1@3130,982.44 ; C9.1@3147.56,990 3147.56,1037.56 3160,1050 3160,1090.15 3153.65,1096.5 3153.65,1101.43 3151.59,1103.49 3151.59,1103.84 3151,1104.43 3151,1129 3149.53,1130.47 U2.27@3149.53,1145.83
CS2: C34.2 R29.1 U2.4 | length 203.3
  Top Layer w9.5: U2.4@3149.53,1374.17 3149.53,1449.53 3167.56,1467.56 C34.2@3167.56,1500 R29.1@3167.56,1570
DEMB: R20.2 R21.2 U2.33 | length 549.3
  Top Layer w9: U2.33@3234.17,1210.79 3299.21,1210.79 v2(3320,1190) ; R21.2@3657.56,1190 v1(3700,1190) R20.2@3732.44,1190
  Bottom Layer w9: v2(3320,1190) v1(3700,1190)
EN1: R15.2 TP6.1 U2.31 | length 677.3
  Top Layer w9: U2.31@3234.17,1171.42 3258.58,1171.42 3330,1100 v1(3340,1100) 3362.44,1100 R15.2@3372.44,1090
  Bottom Layer w9: v1(3340,1100) 3370,1130 3680,1130 3750,1060 3750,1019.49 TP6.1@3759.49,1010
EN2: R24.2 TP8.1 U2.40 | length 635.2
  Top Layer w9.5: U2.40@3234.17,1348.58 3248.58,1348.58 3280,1380 3330,1380 v2(3340,1370) 3350,1380 R24.2@3388.35,1380
  Bottom Layer w9.5: v2(3340,1370) 3370,1400 3660,1400 TP8.1@3750,1490
FB: R3.1 R4.2 R5.1 U2.3 U2.28 | length 1190.3
  Top Layer w9.5: 3169.21,1110.79 U2.28@3169.21,1145.83 ; U2.3@3169.21,1374.17 3169.21,1429.21 v2(3180,1440)
  Top Layer w10: 3169.21,1110.79 3171.27,1108.73 3171.27,1103.8 3180,1095.08 3180,1050 v2(3190,1040) R4.2@3190,997.56 ; R3.1@3190,767.56 v1(3190,810) ; R3.1@3192.44,770 R5.1@3462.44,770
  Signal Layer 4 w9.5: v2(3180,1440) 3200,1420 3200,1122.2 3180,1102.2 3180,1050 v2(3190,1040)
  Signal Layer 4 w10: v1(3190,810) v2(3190,1040)
HB1: C22.2 D2.1 U2.20 | length 293.1
  Top Layer w9.5: D2.1@2800,1146.69 2800,1120 2820,1100 C22.2@2932.44,1100 2932.44,1123.11 2939.33,1130 2980,1130 3005.83,1155.83 U2.20@3005.83,1171.42
HB2: C30.2 D3.1 U2.11 | length 292.7
  Top Layer w9.5: D3.1@2800,1373.31 2800,1400 2820,1420 C30.2@2932.44,1420 2932.44,1397.56 2946.38,1383.62 2986.38,1383.62 3005.83,1364.17 U2.11@3005.83,1348.58
HO1: R10.2 U2.22 | length 1189.6
  Top Layer w9.5: v2(3030,1090) 3032.29,1092.29 3032.29,1107.71 3051.1,1126.53 U2.22@3051.1,1145.83
  Top Layer w20: R10.2@2037.56,770 2070,770 v1(2080,780)
  Signal Layer 4 w20: v1(2080,780) 2100,800 2740,800 v2(3030,1090)
HO2: R35.1 U2.9 | length 1599.8
  Top Layer w9.5: v2(3030,1430) 3030,1420 3051.1,1398.9 U2.9@3051.1,1374.17
  Top Layer w20: R35.1@2007.56,2160 v1(2070,2160)
  Signal Layer 4 w20: v1(2070,2160) 2070,1970 2069.17,1970 2051.13,1951.96 2051.13,1951.13 2050,1950 2050,1910 2200,1760 2750,1760 2920,1590 2920,1540 2945.13,1514.87 2945.13,1504.87 2959.7,1490.3 2969.7,1490.3 v2(3030,1430)
HOL1: R11.2 U2.23 | length 1275.8
  Top Layer w9.5: v2(3050,1060) 3050,1076.59 3053.62,1080.21 3053.62,1103.62 3070.79,1120.79 U2.23@3070.79,1145.83
  Top Layer w20: R11.2@2037.56,710 2070,710 v1(2080,720)
  Signal Layer 4 w20: v1(2080,720) 2125.18,720 2155.43,750.25 2760.61,750.25 2981.48,971.13 3001.96,971.13 3050,1019.17 v2(3050,1060)
HOL2: R36.1 U2.8 | length 1637.2
  Top Layer w9.5: v2(3050,1470) 3050,1443.41 3053.62,1439.79 3053.62,1426.38 ; 3055.62,1424.38 3070.79,1409.21 U2.8@3070.79,1374.17
  Top Layer w20: R36.1@2007.56,2220 v1(2070,2220)
  Signal Layer 4 w20: v1(2070,2220) 2110,2180 2110,1930 2230.25,1809.75 2770.61,1809.75 2970,1610.35 2970,1580 2981.54,1568.46 2982.79,1568.46 3000.87,1550.38 3000.87,1549.13 3010,1540 3010,1510 v2(3050,1470)
ILSET: C24.1 R26.1 R27.1 U2.34 | length 604.1
  Top Layer w9: U2.34@3234.17,1230.47 3319.53,1230.47 v2(3330,1220) 3340,1210 C24.1@3372.44,1210 ; R27.1@3657.56,1250 v1(3700,1250) R26.1@3732.44,1250
  Bottom Layer w9: v2(3330,1220) 3670,1220 v1(3700,1250)
LO1: R12.2 U2.18 | length 381.8
  Top Layer w9.5: v2(2960,1200) 2970.79,1210.79 U2.18@3005.83,1210.79
  Top Layer w20: R12.2@2705.87,1013.27 v1(2758.31,1013.27)
  Signal Layer 4 w20: v1(2758.31,1013.27) 2772.43,1013.27 2959.17,1200 v2(2960,1200)
LO2: R33.1 U2.13 | length 305.2
  Top Layer w9.5: v2(2960,1320) 2970.79,1309.21 U2.13@3005.83,1309.21
  Top Layer w24: R33.1@2717.56,1350 v1(2770,1350)
  Signal Layer 4 w24: v1(2770,1350) 2923.66,1350 2953.66,1320 v2(2960,1320)
LOL1: R13.2 U2.19 | length 403.7
  Top Layer w9.5: v2(2960,1160) 2991.1,1191.1 U2.19@3005.83,1191.1
  Top Layer w20: R13.2@2705.87,953.27 v1(2758.31,953.27)
  Signal Layer 4 w20: v1(2758.31,953.27) 2830,1024.96 2830,1030 v2(2960,1160) v2@2960,1157.75
LOL2: R34.1 U2.12 | length 322.9
  Top Layer w9.5: v2(2960,1360) 2991.1,1328.9 U2.12@3005.83,1328.9
  Top Layer w22: R34.1@2717.56,1410 v1(2770,1410)
  Signal Layer 4 w20: v1@2770.03,1408.92 v1(2770,1410) 2800,1380 2940,1380 v2(2960,1360)
NetC18_2: C18.2 R9.2 | length 112.5
  Bottom Layer w40: R9.2@2353.39,1046.77 2350,1043.39 2350,950.64 C18.2@2360.58,940.06
NetC19_2: C19.2 R16.1 | length 50
  Top Layer w9.5: C19.2@3300,990 R16.1@3300,1040
NetL1_2: L1.2 R7.2 R7A.2 R8.2 | length 3168.9
  Top Layer w10: v1@1000,870 v1(1005,870) 1021.41,870 ; v1(3120,840) 3130,850 R8.2@3130,882.44
  Signal Layer 4 w10: v1(1005,870) 1775,100 2995.28,100 3110,214.72 3110,826.24 3120,836.24 v1(3120,840)
NetL2_1: L2.1 R29.2 R30.1 R30A.1 | length 3243.3
  Top Layer w10: v1@1010,1650 1029.25,1650 ; v1(3140,1690) 3170,1660 R29.2@3170,1627.56
  Signal Layer 4 w10: v1(1005,1650) 1110,1650 1930,2470 2960,2470 3140,2290 v1(3140,1690)
NetPG1_2: PG1.2 R14.1 | length 360.7
  Top Layer w9.5: v1(3030,550) R14.1@3030,592.44
  Bottom Layer w9.5: v1(3030,550) 3240,550 3260,570 PG1.2@3340,570
NetPG2_2: PG2.2 R25.2 | length 130.2
  Top Layer w9.5: R25.2@3215.29,1986.7 3256.7,1986.7 3270,2000 PG2.2@3340,2000
NetQ1_1: Q1.1 R10.1 R11.1 | length 138.9
  Top Layer w24: R10.1@1982.44,770 R11.1@1982.44,710 1982.44,661.5 Q1.1@2003.94,640
NetQ2_1: Q2.1 R12.1 R13.1 | length 200.1
  Top Layer w24: Q2.1@2536.06,920 2637.4,920 2650.75,933.35 R13.1@2650.75,953.27 R12.1@2650.75,1013.27
NetQ3_1: Q3.1 R35.2 R36.2 | length 177.1
  Top Layer w20: R36.2@1952.44,2220 R35.2@1952.44,2160 1952.44,2097.56 1960,2090 Q3.1@2003.94,2090
NetQ4_1: Q4.1 R33.2 R34.2 | length 196.4
  Top Layer w24: Q4.1@2536.06,1420 2662.44,1420 R33.2@2662.44,1350
NetR1_2: R1.2 U1.1 U1.4 | length 331.9
  Top Layer w10: R1.2@3322.44,1490 v1(3380,1490) 3382.6,1492.6 U1.1@3382.6,1525.87 U1.1@3378.46,1530 ; U1.4@3457.4,1634.13 3494.13,1634.13 v1(3498.27,1630)
  Bottom Layer w10: v1(3380,1490) 3498.27,1608.27 v1(3498.27,1630)
NetR2_1: R2.1 R3.2 TP9.1 | length 144.9
  Top Layer w10: R2.1@3190,567.56 TP9.1@3190,640 R3.2@3190,712.44
OSC: R17.1 R18.1 U2.37 | length 569.9
  Top Layer w9: U2.37@3234.17,1289.53 3299.53,1289.53 v2(3330,1320)
  Top Layer w9.5: R18.1@3657.56,1350 v1(3700,1350) 3722.44,1350 R17.1@3732.44,1340
  Bottom Layer w9.5: v2(3330,1320) 3670,1320 3690,1340 v1(3700,1350)
PG1: PG1.1 R14.2 U2.24 | length 841.6
  Top Layer w9.5: R14.2@3030,647.56 v1(3030,690) 3030,990 3080,1040 v2(3080,1080) 3080,1103.41 3090.47,1113.88 U2.24@3090.47,1145.83
  Bottom Layer w9.5: v1(3030,690) 3250,690 3270,670 PG1.1@3340,670
PG2: PG2.1 R25.1 U2.7 | length 817.6
  Top Layer w9.5: 3090.21,1416.38 3076.38,1430.21 3076.38,1503.62 3050,1530 3050,1681.95 3050,1830 3151.58,1931.58 R25.1@3215.29,1931.58 3258.42,1931.58 3290,1900 PG2.1@3340,1900 ; U2.7@3090.47,1374.17 3090.47,1416.38
RES: C26.1 U2.32 | length 155.3
  Top Layer w9: U2.32@3234.17,1191.1 3268.9,1191.1 3310,1150 C26.1@3372.44,1150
